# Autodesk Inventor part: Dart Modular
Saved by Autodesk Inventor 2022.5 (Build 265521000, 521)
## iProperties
Created: 2025-01
Part Number: Dart Modular
Material: Generic
Document SubType Name: Modeling
Designer: AdminForWorker
Density: 1 g/cm^3
Appearance: Default
Title: Dart Modular
Author: AdminForWorker
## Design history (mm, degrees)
feature "Dart Modular"
body "Solid1"
